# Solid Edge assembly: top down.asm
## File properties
Title: Yoke
Author: Abhinav Rai
Template: normal.par
Last saved by: Cadcim
Revision: 17
Application: Solid Edge
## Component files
u-joint.par
swivel.par
bushing1.par
ret ring.par
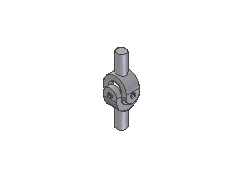
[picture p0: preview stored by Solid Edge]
